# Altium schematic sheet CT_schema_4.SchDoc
size 193 x 163 mm
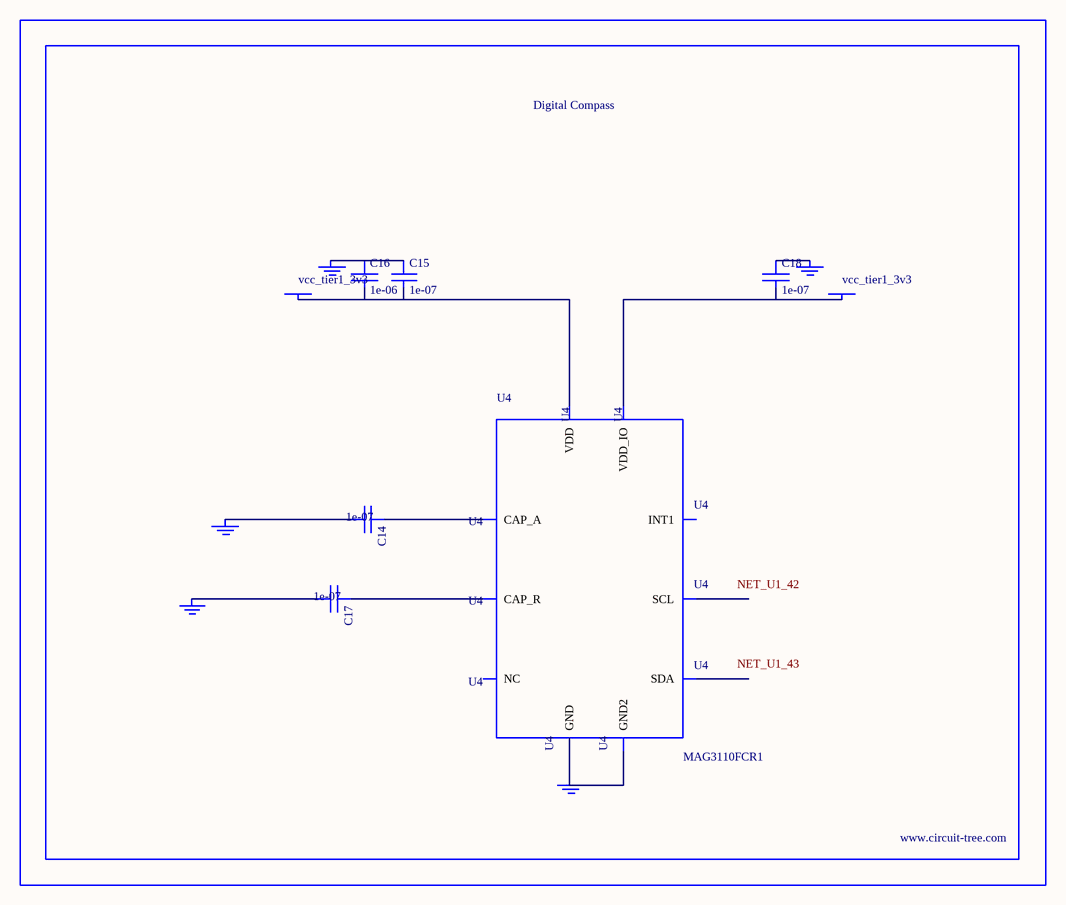
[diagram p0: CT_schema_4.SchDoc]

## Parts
BORDER3  (no value)
C14  1e-07  [C0402]
C15  1e-07  [C0402]
C16  1e-06  [C0603]
C17  1e-07  [C0402]
C18  1e-07  [C0402]
GND_INSTANCE_3_0  (no value)
GND_INSTANCE_3_1  (no value)
GND_INSTANCE_3_2  (no value)
GND_INSTANCE_3_3  (no value)
GND_INSTANCE_3_4  (no value)
POWER_INSTANCE_3_0  vcc_tier1_3v3
POWER_INSTANCE_3_1  vcc_tier1_3v3
U4  MAG3110FCR1  [DFN-10]

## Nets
NetC14_1: C14.1 U4.1(CAP_A)
NetC14_2: C14.2 GND_INSTANCE_3_0.0(GND)
NetC15_1: C15.1 C16.1 GND_INSTANCE_3_1.0(GND)
NetC15_2: C15.2 C16.2 POWER_INSTANCE_3_0.0(PWR) U4.2(VDD)
NetC17_1: C17.1 U4.4(CAP_R)
NetC17_2: C17.2 GND_INSTANCE_3_2.0(GND)
NetC18_1: C18.1 GND_INSTANCE_3_3.0(GND)
NetC18_2: C18.2 POWER_INSTANCE_3_1.0(PWR) U4.8(VDD_IO)
NetGND_INSTANCE_3_4_0: GND_INSTANCE_3_4.0(GND) U4.5(GND) U4.10(GND2)

Not connected (* = marked no-connect by the designer): U4 3(NC) 6(SDA) 7(SCL) 9(INT1)

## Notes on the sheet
- Labels drawn without touching a wire or pin: NET_U1_42, NET_U1_43

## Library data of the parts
BORDER3 = BORDER_PAGE3
C14 C15 C17 C18 = C0402C104K3RACTU
C16 = C0603C105K3RACTU
GND_INSTANCE_3_0-GND_INSTANCE_3_4 = GND
POWER_INSTANCE_3_0 POWER_INSTANCE_3_1 = PWR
